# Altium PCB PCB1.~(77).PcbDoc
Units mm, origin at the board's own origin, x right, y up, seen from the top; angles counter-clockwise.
Board outline 68 x 68 mm, 2 copper layers (Top Layer, Bottom Layer); 33 components, 24 nets, 105 pads, 18 vias.
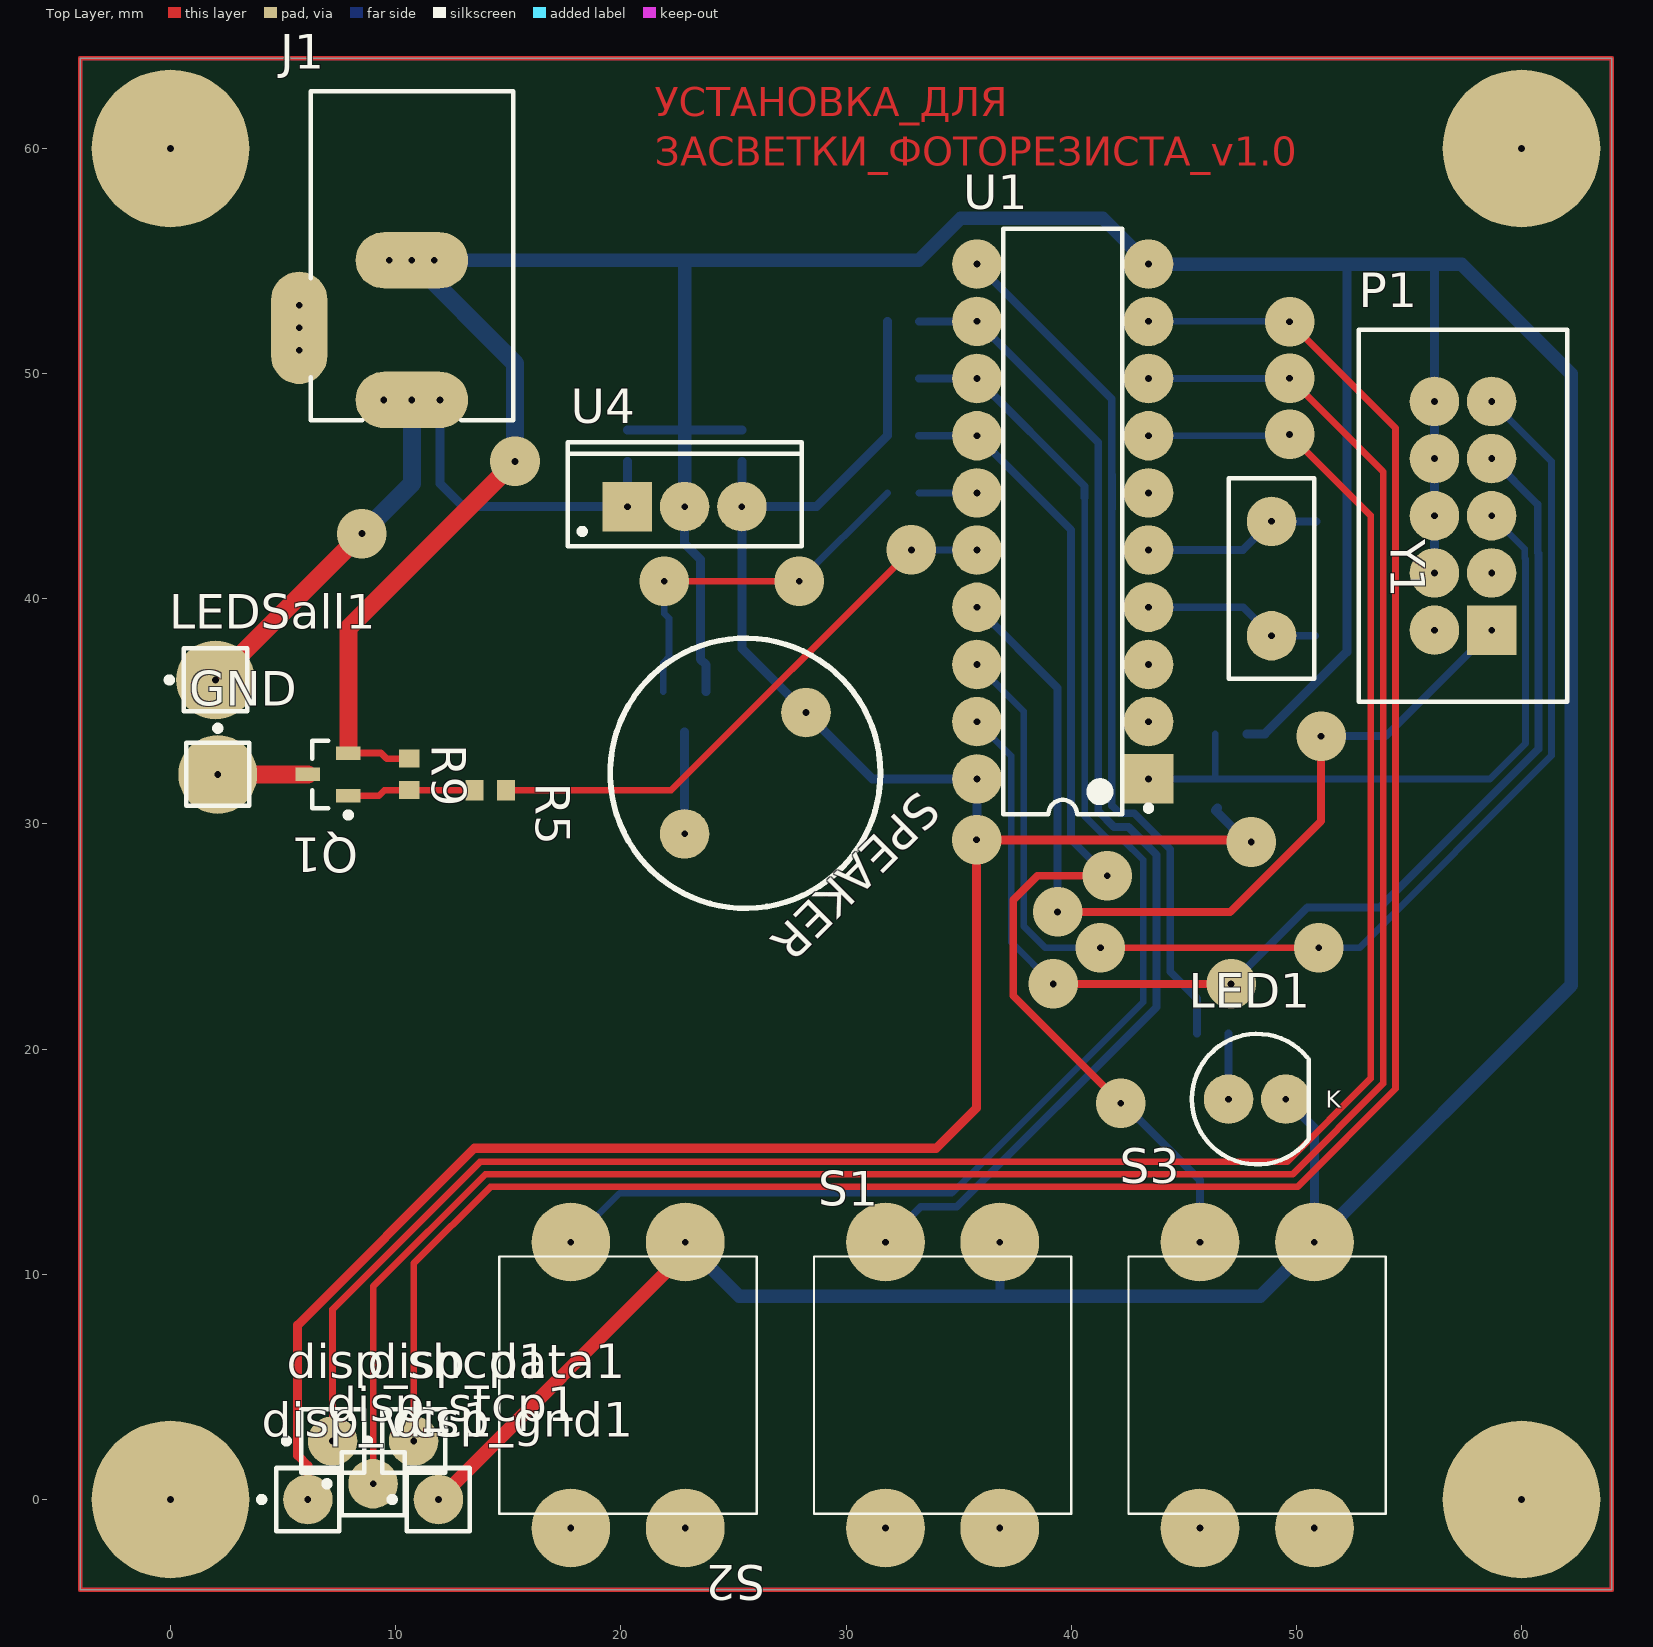
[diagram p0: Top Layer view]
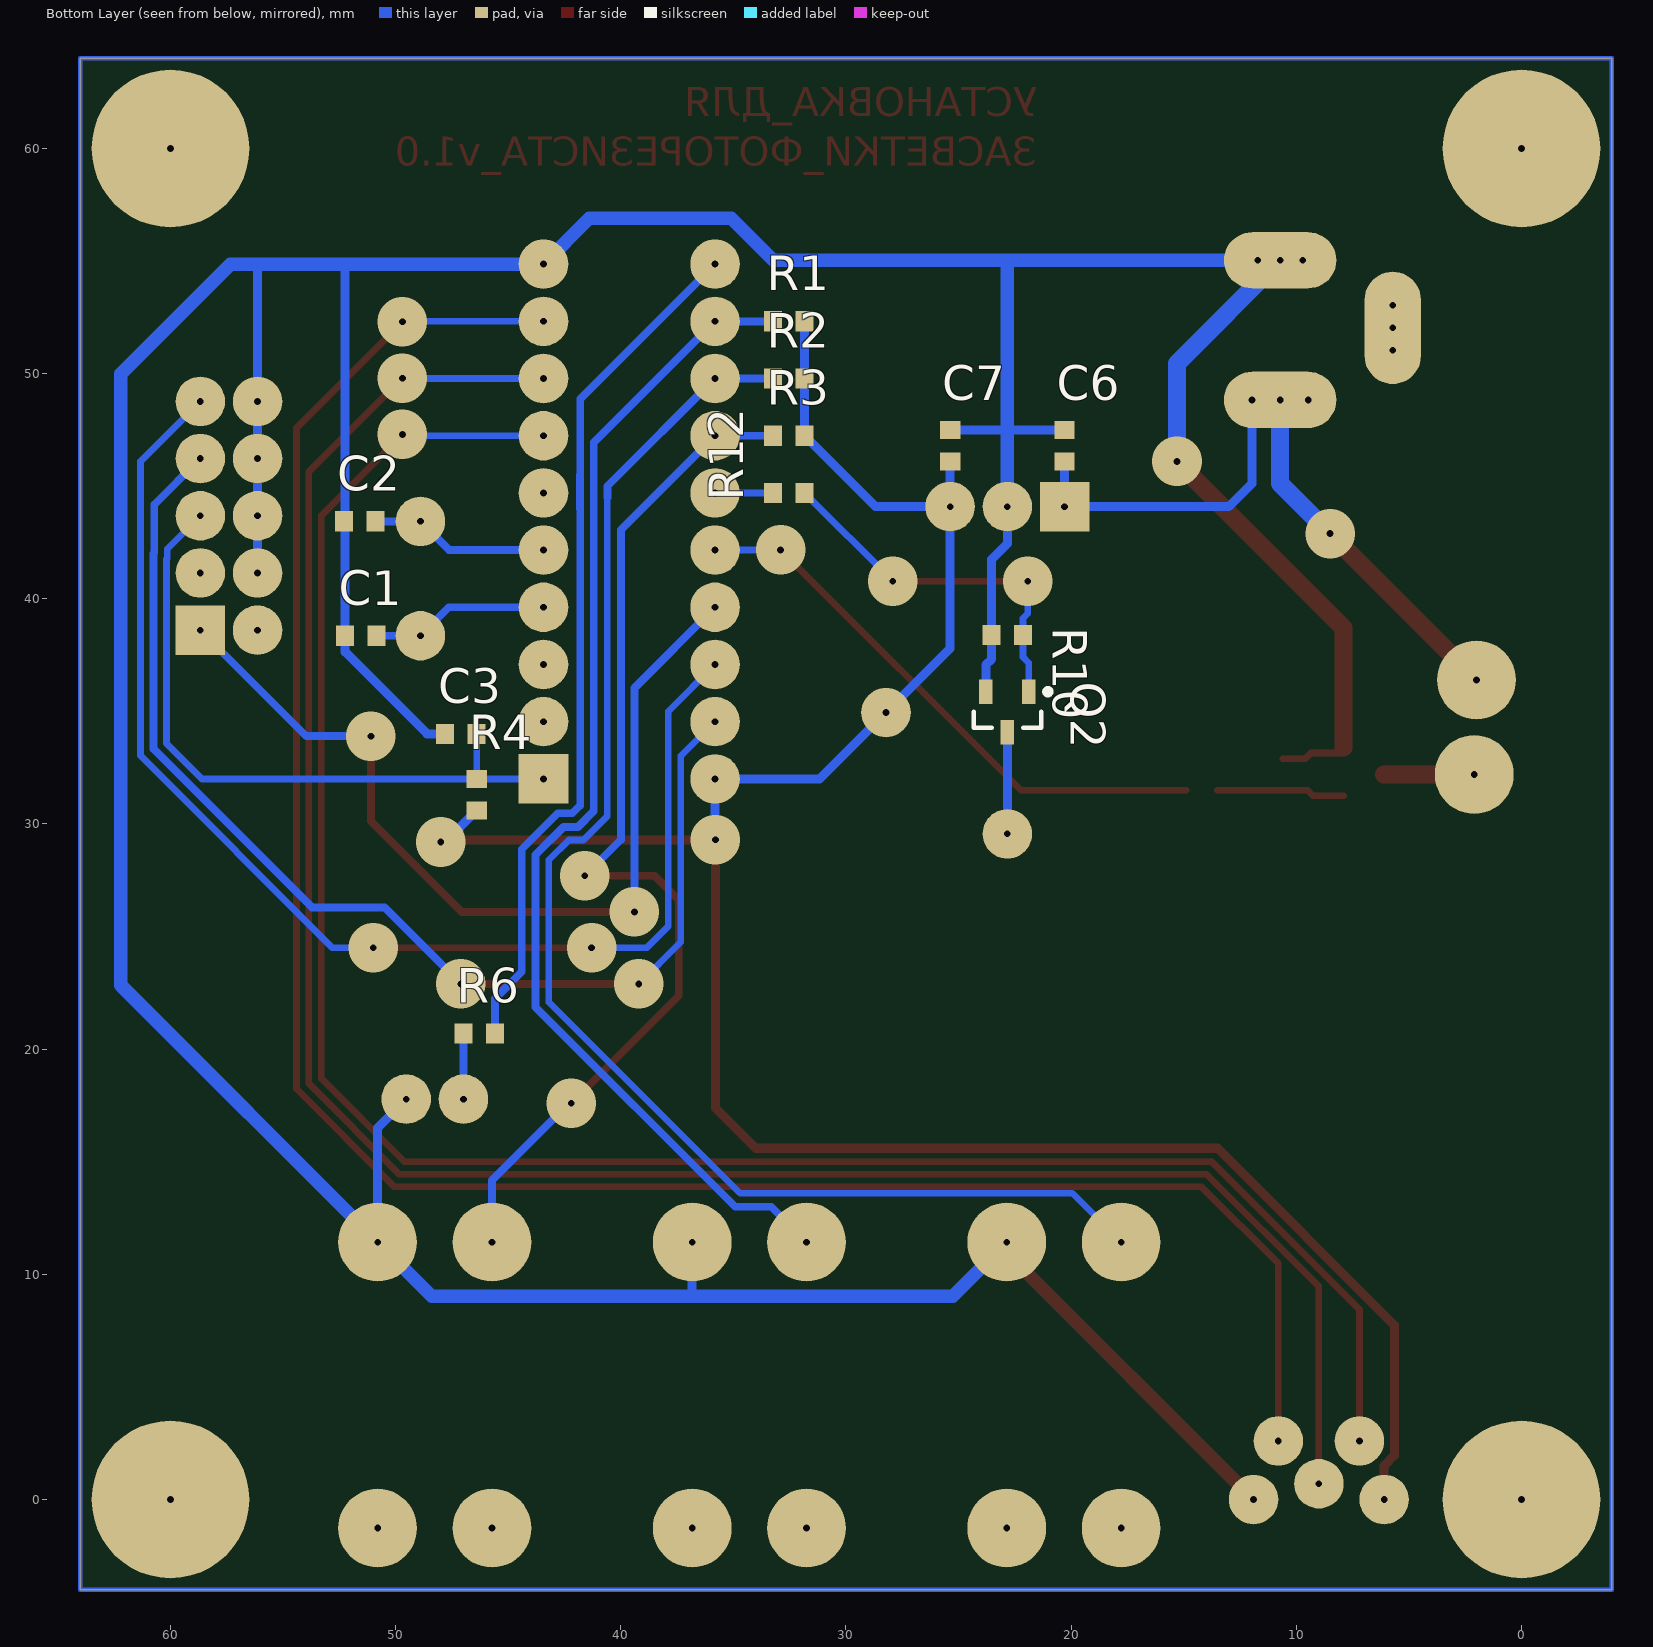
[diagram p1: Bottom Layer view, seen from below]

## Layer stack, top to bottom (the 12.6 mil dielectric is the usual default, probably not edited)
Top Solder: solder mask 0.0102, Solder Resist, Dk 3.5
Top Layer: signal copper 0.0356
Dielectric 1: dielectric 0.32, FR-4, Dk 4.8
Bottom Layer: signal copper 0.0356
Bottom Solder: solder mask 0.0102, Solder Resist, Dk 3.5

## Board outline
-4,-4 64,-4 64,64 -4,64

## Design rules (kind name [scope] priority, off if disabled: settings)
Clearance Clearance_U1_1 [InComponent('U1') vs IsRegion] p1: gap=0.254
Clearance Clearance_U1 [InComponent('U1') vs OnLayer('Top Layer')] p2: gap=0.178
Clearance [All] p3: gap=0.254
MinimumSolderMaskSliver [All] p1 off: minsoldermaskwidth=0.254
PasteMaskExpansion [All] p1 off: expansion=0
PolygonConnect [All] p1: connectstyle=Relief reliefconductorwidth=0.254 reliefentries=4 polygonreliefangle="90 Angle" airgapwidth=0.254
RoutingVias [All] p1: holewidth=0.711 width=1.27 viastyle="Through Hole" minholewidth=0.254 minwidth=0.508 maxholewidth=0.762 maxwidth=5
SolderMaskExpansion [All] p1 off: expansion=0.102
Width [All] p1: maxlimit=5 minlimit=0.3 preferedwidth=0.35
28 further rules are at their usual default settings.

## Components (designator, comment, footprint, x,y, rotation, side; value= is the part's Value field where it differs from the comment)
C1 "Cap Semi" CAPC1608L 51.54,38.36 r180 bottom
C2 "Cap Semi" CAPC1608L 51.6,43.44 r180 bottom
C3 "Cap Semi" CAPC1608L 47.1,34 r0 bottom
C6 "Cap Semi" CAPC1608L 20.3,46.8 r270 bottom
C7 "Cap Semi" CAPC1608L 25.375,46.8 r270 bottom
disp_data1 "uleds_all" PIN1#1 10.8,2.6 r90 top
disp_gnd1 "uleds_all" PIN1#1 11.9,0 r90 top
disp_shcp1 "uleds_all" PIN1#1 7.2,2.6 r90 top
disp_stcp1 "uleds_all" PIN1#1 9,0.7 r90 top
disp_vcc1 "uleds_all" PIN1#1 6.1,0 r90 top
GND "GNDout" PIN1#2 2.1,32.2 r0 top
J1 "PWR2.5" PCBComponent_1 10.719,54.915 r270 top
LED1 "151051YS04000" "Type 5mm" 48.26,17.78 r0 top
LEDSall1 "uleds_all" PIN1#2 2,36.4 r90 top
P1 "ZSS-105-01-F-D-450" SMTC-ZSS-105-01-X-D-450 58.674,38.608 r90 top
Q1 "IRLML0060TRPBF" NXP-SOT23_L 7,32.2 r180 top
Q2 "IRLML0060TRPBF" NXP-SOT23_L 22.835,34.975 r270 bottom
R1 "Res3" CAPC1608L 32.537,52.324 r0 bottom
R2 "Res3" CAPC1608L 32.537,49.784 r0 bottom
R3 "Res3" CAPC1608L 32.537,47.244 r0 bottom
R4 "Res3" CAPC1608L 46.4,31.304 r90 bottom
R5 "Res3" CAPC1608L 14.2,31.5 r0 top
R6 "Res3" CAPC1608L 46.29,20.701 r0 bottom
R9 "Res3" CAPC1608L 10.6,32.2 r270 top
R10 "Res3" CAPC1608L 22.835,38.397 r180 bottom
R12 "Res3" CAPC1608L 32.537,44.704 r0 bottom
S1 "START_min" key 34.29,5.08 r180 top
S2 "START_all" key 20.32,5.08 r180 top
S3 "PAUSE" key 48.26,5.08 r180 top
SPEAKER "speaker" speaker 25.529,32.256 r225 top
U1 "ATtiny2313V-10PU" 20P3 39.624,43.434 r180 top
U4 "MC78M05CTG" TO220 22.835,44.094 r0 top
Y1 "16MHz" "PCBComponent_1 - duplicate" 48.9,40.9 r0 top

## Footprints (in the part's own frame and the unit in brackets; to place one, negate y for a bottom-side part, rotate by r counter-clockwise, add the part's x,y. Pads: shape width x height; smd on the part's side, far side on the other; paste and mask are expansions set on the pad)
20P3 [mm] "DIP, 20-Pin, Row Spacing 7.62 mm, Pitch 2.54 mm"
  rect 2.2x2.2 hole 0.3: 1(-3.81,11.43)
  round 2.2 hole 0.3: 2(-3.81,8.89) 3(-3.81,6.35) 4(-3.81,3.81) 5(-3.81,1.27) 6(-3.81,-1.27) 7(-3.81,-3.81) 8(-3.81,-6.35) 9(-3.81,-8.89) 10(-3.81,-11.43) 11(3.81,-11.43) 12(3.81,-8.89) 13(3.81,-6.35) 14(3.81,-3.81) 15(3.81,-1.27) 16(3.81,1.27) 17(3.81,3.81) 18(3.81,6.35) 19(3.81,8.89) 20(3.81,11.43)
  silkscreen extent -3.94,-13 2.65,13, body extent -3.6,-12.95 3.6,12.95, height 5.08
CAPC1608L [mm] "Chip Capacitor, Body 1.6x0.8mm, IPC High Density"
  rect 0.8x0.9 smd: 1(-0.7,0) 2(0.7,0)
  body extent -0.87,-0.48 0.87,0.48, height 1.3
key [mm]
  round 3.5 hole 0.3: 1(2.54,-6.35) 2(-2.54,-6.35) 3(-2.54,6.35) 4(2.54,6.35)
  silkscreen extent -5.72,-5.72 5.72,5.72, body extent -6.35,-6.35 6.35,6.35, height 11.94
NXP-SOT23_L [mm] "SOT23, 3-Leads, Body 3x1.4mm, Pitch 0.95mm, IPC High Density"
  rect 1.1x0.6 smd: 1(-0.9,0.95) 2(-0.9,-0.95) 3(0.9,0)
  silkscreen extent -1.03,-1.5 0.7,1.92, body extent -0.7,-1.5 0.7,1.5, height 1.1
PCBComponent_1 [mm]
  oval 2.5x5 hole 0.3: 1(6.08,0) 2(-0.12,0)
  round 1.5 hole 0.3: 1A(6.08,-1.25) 1B(6.08,1.25) 2A(-0.12,-1) 2B(-0.12,1) 3A(1.88,-5) 3B(3.88,-5)
  oval 5x2.5 hole 0.3: 3(2.88,-5)
  silkscreen extent -7.62,-4.5 6.98,4.5, body extent -7.87,-5.6 6.83,5.6, height 11
"PCBComponent_1 - duplicate" [mm]
  round 2.2 hole 0.3: 1(0,-2.54) 2(0,2.54)
  silkscreen extent -1.91,-4.44 1.91,4.44, body extent -2.33,-5.67 2.32,5.68, height 3.6
PIN1#1 [mm] "Connector; Plug"
  round 2.2 hole 0.3: 1(0,0)
  silkscreen extent -1.4,-1.4 1.4,2.17
PIN1#2 [mm] "Connector; Plug"
  round 3.5 hole 0.3: 1(0,0)
  silkscreen extent -1.4,-1.4 1.4,2.17
SMTC-ZSS-105-01-X-D-450 [mm] "Shrouded .025\" SQ Post Header, 2x5 Pins, Vertical, 2.54mm Pitch, Male"
  rect 2.2x2.2 hole 0.3: 1(0,0)
  round 2.2 hole 0.3: 2(0,2.54) 3(2.54,0) 4(2.54,2.54) 5(5.08,0) 6(5.08,2.54) 7(7.62,0) 8(7.62,2.54) 9(10.16,0) 10(10.16,2.54)
  silkscreen extent -3.18,-3.36 13.33,5.9, body extent -3.17,-3.57 13.34,5.91, height 11.43
speaker [mm]
  round 2.2 hole 0.3: 0(3.81,0) 1(-3.81,0)
  silkscreen extent -6,-6 6,6, body extent -6,-6 6,6, height 9.5
TO220 [mm] "TO, Thru-Hole, Vertical, Heatsink Mounted; 3 In-Line Leads; Pitch 2.54 mm"
  rect 2.2x2.2 hole 0.3: 1(-2.54,0)
  round 2.2 hole 0.3: 2(0,0) 3(2.54,0)
  silkscreen extent -5.2,-1.75 5.2,2.85, body extent -5.25,-1.8 5.25,2.9, height 19.7
"Type 5mm" [mm] "THT, LED-5mm, 2pin- Body 5.8mm"
  round 2.2 hole 0.3: 1(1.27,0) 2(-1.27,0)
  silkscreen extent -2.9,-2.9 2.29,2.9, body extent -2.9,-2.9 2.5,2.9, height 11.7

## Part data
C1 C2 C3 C6 C7: "Capacitor (Semiconductor SIM Model)"
disp_data1 disp_gnd1 disp_shcp1 disp_stcp1 disp_vcc1 GND LEDSall1: library part Plug, "Plug"
J1: "Low Voltage Power Supply Connector"
LED1: library part CMP-1488-00010-1, "THT LED round mono-color color lens, WL-TMRW, Yellow"
P1: library part CMP-1024-00461-1
Q1 Q2: library part CMP-1259-00081-1, "N-Channel Trench MOSFET, 60 V, 0.36 A, -55 to 150 degC, 3-Pin SOT23, Tape and Reel"
R1 R2 R3 R4 R5 R6 R9 R10 R12: "Resistor"
S1 S2 S3: library part SW-DPST, "Double-Pole, Single-Throw Switch"
U1: library part CMP-0093-00017-1, "Low Power tinyAVR® 8-Bit Microcontroller, 2K Flash Memory, 10MHz, Industrial Temperature, 20-Lead PDIP, Pb-Free"
U4: library part CMP-0244-00483-1, "Positive Voltage Regulator, 5V, 3-Pin TO-220"
Y1: library part XTAL, "Crystal Oscillator"

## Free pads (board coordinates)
  round 7 hole 0.3: 4(0,0) 5(60,0) 7(60,60) 8(0,60)

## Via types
v1: diameter 2.2, hole 0.3, Top Layer to Bottom Layer, 18 vias

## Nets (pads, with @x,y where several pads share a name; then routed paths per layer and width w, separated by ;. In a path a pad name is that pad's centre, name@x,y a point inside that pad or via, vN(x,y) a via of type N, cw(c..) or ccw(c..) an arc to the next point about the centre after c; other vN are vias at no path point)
+24V: C6.2 J1.1 J1.1A J1.1B LEDSall1.1 U4.1 | length 31.8
  Top Layer w0.8: LEDSall1.1 v1(8.5,42.9)
  Bottom Layer w0.4: J1.1B 11.969,45.131 13.006,44.094 U4.1 ; U4.1@20.3,44.1 C6.2
  Bottom Layer w0.8: v1(8.5,42.9) 10.719,45.119 J1.1
  Bottom Layer w1: J1.1 J1.1B
BUT_PAUSE: R3.2 S3.1 U1.14 | length 47.8
  Top Layer w0.35: v1(41.6,27.7) 38.5,27.7 37.426,26.626 37.426,22.374 v1(42.2,17.6)
  Bottom Layer w0.35: R3.2 U1.14 40,43.058 40,29.3 v1(41.6,27.7) ; v1(42.2,17.6) 42.3,17.6 45.72,14.18 S3.1
BUT_START: R1.2 S1.1 U1.12 | length 53.1
  Bottom Layer w0.35: S1.1 33.32,13 34.919,13 43.796,21.877 43.796,28.623 42.548,29.871 41.906,29.871 41.2,30.577 41.2,44.246 41.204,44.25 41.204,45.248 41.2,45.252 41.2,46.938 U1.12 R1.2
BUT_STARTALL: R2.2 S2.1 U1.13 | length 63.5
  Bottom Layer w0.3: S2.1 19.95,13.6 34.7,13.6 43.2,22.1 43.2,28.4 42.308,29.292 41.666,29.292 40.6,30.358 40.6,44.5
  Bottom Layer w0.35: R2.2 U1.13 40.6,44.998 40.6,44.5
DISP_DATA: disp_data1.1 U1.9 | length 97
  Top Layer w0.3: disp_data1.1 10.8,10.479 14.209,13.888 50.055,13.888 54.408,18.241 54.408,47.592 v1(49.7,52.3)
  Bottom Layer w0.3: U1.9 49.676,52.324 v1(49.7,52.3)
DISP_SHCP: disp_shcp1.1 U1.7 | length 92.6
  Top Layer w0.3: disp_shcp1.1 7.2,8.446 13.75,14.996 49.596,14.996 53.3,18.7 53.3,43.7 v1(49.7,47.3)
  Bottom Layer w0.3: U1.7 49.644,47.244 v1(49.7,47.3)
DISP_STCP: disp_stcp1.1 U1.8 | length 96.7
  Top Layer w0.3: disp_stcp1.1 9,9.462 13.98,14.442 49.825,14.442 53.854,18.471 53.854,45.646 v1(49.7,49.8)
  Bottom Layer w0.3: U1.8 49.684,49.784 v1(49.7,49.8)
GND: C1.1 C2.1 C3.2 C6.1 C7.1 disp_gnd1.1 J1.2 J1.2A J1.2B LED1.1 P1.4 P1.6 P1.8 P1.10 Q1.2 Q2.2 R9.1 R10.1 S1.2 S2.2 S3.2 U1.10 U4.2 | length 244.3
  Top Layer w0.3: Q1.2 9.35,33.15 9.6,32.9 R9.1
  Top Layer w0.6: disp_gnd1.1 22.86,10.96 S2.2
  Top Layer w0.8: Q1.2@7.9,33.4 7.9,38.7 v1(15.3,46.1)
  Bottom Layer w0.4: C6.1 22.835,47.5 C7.1 ; U4.2 22.835,42.448 23.535,41.748 R10.1 23.535,37.32 23.785,37.07 Q2.2 ; 36.83,9.03 S1.2 ; C3.2 48.6,34 52.24,37.64 52.24,54.864 ; LED1.1 50.8,16.51 S3.2 ; P1.4 P1.6 P1.8 P1.10 56.134,54.7
  Bottom Layer w0.6: J1.2B 22.835,55.035 ; U4.2 22.835,55.035 ; S2.2 25.26,9.03 36.83,9.03 48.4,9.03 S3.2 62.2,22.83 62.2,50 57.336,54.864 U1.10 41.398,56.9 35.1,56.9 33.235,55.035 22.835,55.035
  Bottom Layer w0.8: J1.2B J1.2 15.3,50.454 v1(15.3,46.1)
MISO: P1.9 U1.18 | length 56.7
  Top Layer w0.3: v1(41.3,24.5) 41.304,24.504 50.996,24.504 v1(51,24.5)
  Bottom Layer w0.3: U1.18 37.892,35.006 37.892,25.473 38.865,24.5 v1(41.3,24.5) ; v1(51,24.5) 52.8,24.5 61.336,33.036 61.336,46.106 P1.9
MOSI: P1.1 U1.17 | length 41.7
  Top Layer w0.35: v1(39.396,26.096) 47.058,26.096 51.1,30.138 v1(51.1,33.9)
  Bottom Layer w0.35: U1.17 39.396,36.042 v1(39.396,26.096) ; v1(51.1,33.9) 53.966,33.9 P1.1
NetC1_2: C1.2 U1.4 Y1.1 | length 7.9
  Bottom Layer w0.35: U1.4 47.636,39.624 Y1.1 C1.2
NetC2_2: C2.2 U1.5 Y1.2 | length 8
  Bottom Layer w0.35: U1.5 47.624,42.164 Y1.2 C2.2
NetGND_1: GND.1 Q1.3 | length 4
  Top Layer w0.8: GND.1 Q1.3
NetJ1_3: J1.3 J1.3A J1.3B
NetLED1_2: LED1.2 R6.2 | length 2.9
  Bottom Layer w0.35: LED1.2 R6.2
NetQ1_1: Q1.1 R5.1 R9.2 | length 5.7
  Top Layer w0.3: Q1.1 9.25,31.25 9.5,31.5 R9.2 R5.1
NetQ2_1: Q2.1 R10.2 R12.1 | length 16.6
  Top Layer w0.3: v1(21.93,40.782) v1(27.922,40.782)
  Bottom Layer w0.3: Q2.1 21.885,37.159 22.135,37.409 R10.2 22.135,39.138 21.93,39.342 v1(21.93,40.782) ; v1@27.922,40.788 R12.1
  Bottom Layer w0.4: v1(27.922,40.782) v1@27.922,40.788
NetQ2_3: Q2.3 SPEAKER.0 | length 4.5
  Bottom Layer w0.4: SPEAKER.0 Q2.3
NetR6_1: R6.1 U1.11 | length 38.6
  Bottom Layer w0.35: U1.11 41.804,48.874 41.804,45.502 41.808,45.498 41.808,44 41.804,43.996 41.804,30.827 42.156,30.475 42.798,30.475 44.4,28.873 44.4,23.438 45.59,22.248 R6.1
RES: C3.1 P1.5 R4.2 U1.1 | length 30.1
  Bottom Layer w0.3: U1.1 R4.2 ; C3.1 R4.2 ; P1.5 60.142,42.22 60.142,41.807 60.178,41.771 60.178,33.578 58.604,32.004 R4.2
SCK: P1.7 U1.19 | length 52.7
  Top Layer w0.35: v1(39.2,22.9) v1(47.1,22.9)
  Bottom Layer w0.3: U1.19 37.338,33.02 37.338,24.762 v1(39.2,22.9)
  Bottom Layer w0.35: v1(47.1,22.9) 50.5,26.3 53.719,26.3 60.757,33.338 60.757,40.115 60.757,40.285 60.757,42.011 60.721,42.047 60.721,44.181 P1.7
SPEAKER: R12.2 U1.15 | length 2.6
  Bottom Layer w0.3: R12.2 U1.15
ULEDS: R5.2 U1.16 | length 25.3
  Top Layer w0.3: R5.2 22.234,31.5 v1(32.904,42.17)
  Bottom Layer w0.3: v1(32.904,42.17) 35.808,42.17 U1.16 U1.16@35.808,42.164
VCC: C7.2 disp_vcc1.1 R1.1 R2.1 R3.1 R4.1 SPEAKER.1 U1.20 U4.3 | length 106.1
  Top Layer w0.4: disp_vcc1.1 6.1,1.502 5.646,1.956 5.646,7.746 13.5,15.6 34.003,15.6 35.8,17.397 v1(35.8,29.3) 47.9,29.3 v1(48,29.2)
  Bottom Layer w0.3: SPEAKER.1@28.429,34.474 SPEAKER.1@28.429,34.95
  Bottom Layer w0.4: C7.2 U4.3 ; R1.1 R2.1 R3.1 28.688,44.094 U4.3 ; v1(35.8,29.3) 35.528,29.3 35.814,29.586 U1.20 31.169,32.004 25.375,37.798 U4.3 ; R4.1@46.498,30.702 R4.1 47.804,29.2 v1(48,29.2)
pads on no net: P1.2 P1.3 S1.3 S1.4 S2.3 S2.4 S3.3 S3.4 U1.2 U1.3 U1.6
copper on no net: | length 544
  Top Layer w0.2: -4,-4 -4,64 64,64 64,-4 -4,-4
  Bottom Layer w0.2: -4,-4 -4,64 64,64 64,-4 -4,-4

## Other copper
Top Layer:
  text "УСТАНОВКА_ДЛЯ / ЗАСВЕТКИ_ФОТОРЕЗИСТА_v1.0" at 21.5,58.8 h2.2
